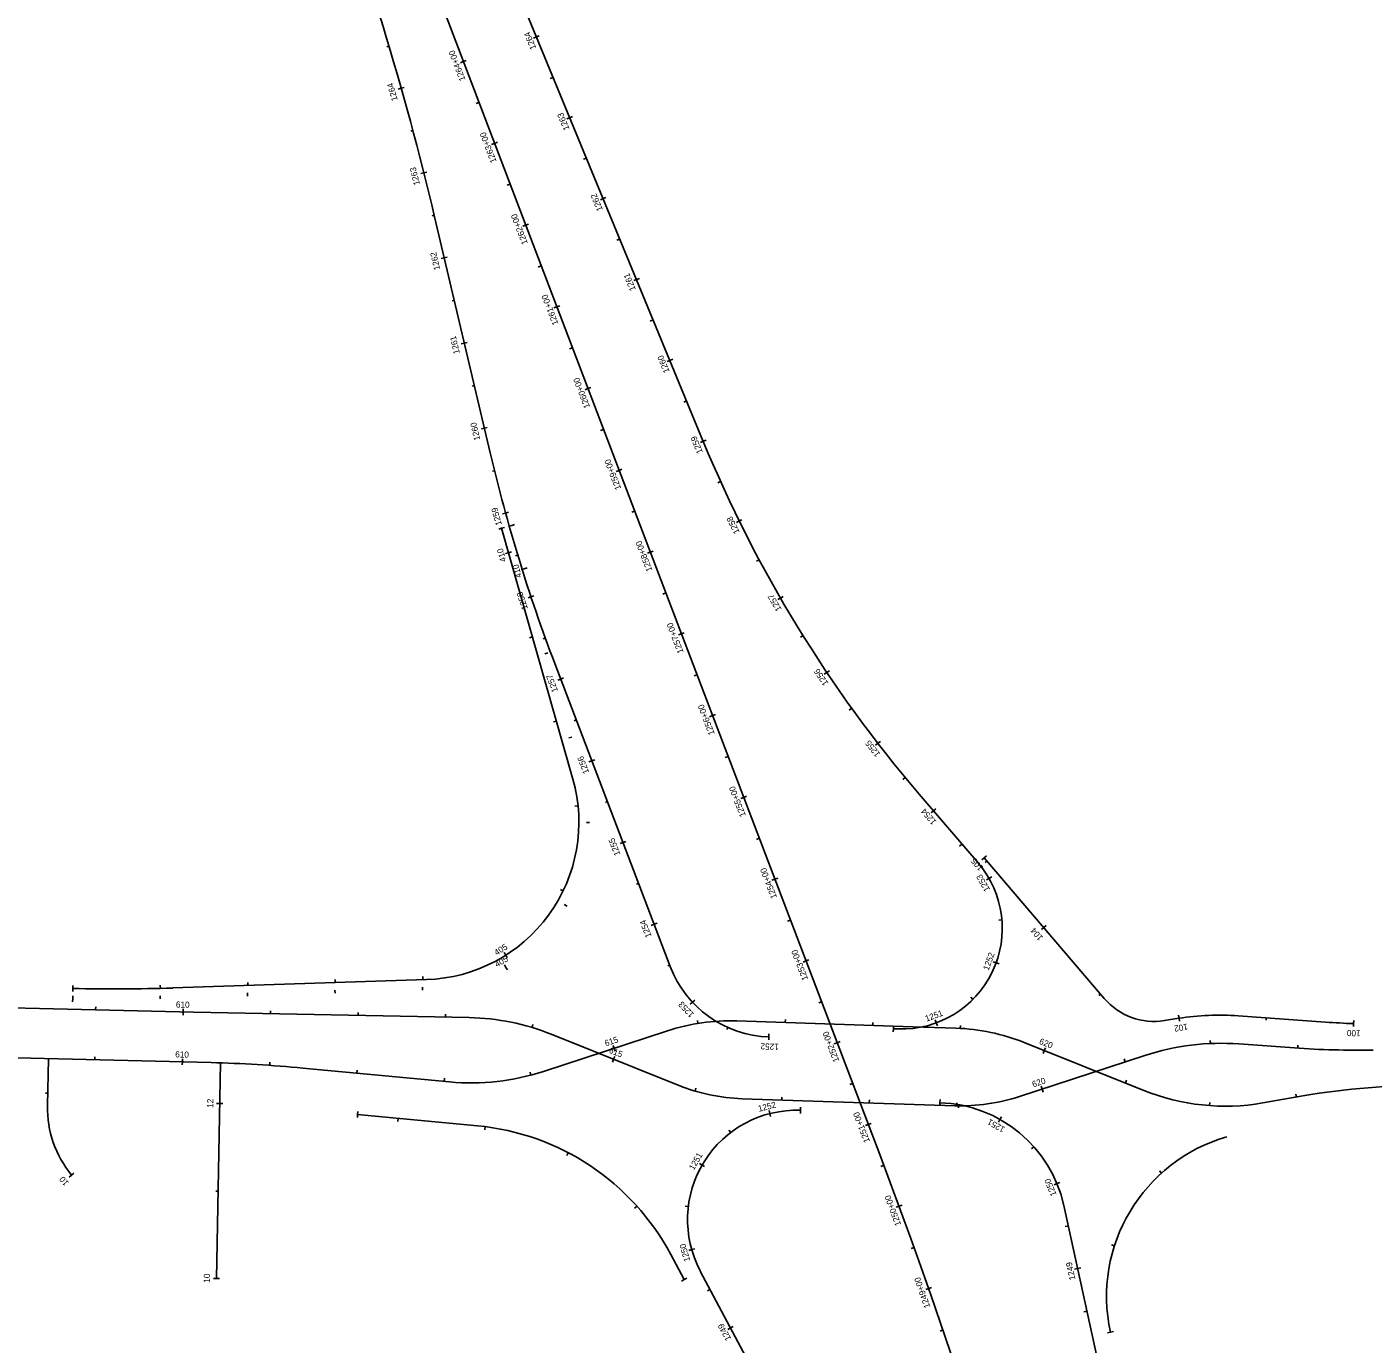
# Model space of a CAD drawing. Extents: x 596008 to 607538, y 326212 to 405053.
# Drawn here: x 602999 to 604538, y 349610 to 351115 of the extents above; entities that cross this region are included whole.
import ezdxf

# ---------------------------------------------------------------- set-up
doc = ezdxf.new("R2010")
doc.units = 0
for name, color, linetype in [('P_ALI', 7, 'Continuous'), ('P_ALI_200', 7, 'Continuous'), ('P_ALI_200_Sta', 7, 'Continuous'), ('P_ALI_200_Tic', 7, 'Continuous')]:
    doc.layers.add(name, color=color, linetype=linetype)

msp = doc.modelspace()

# ---------------------------------------------------------------- linework, layer by layer
at = {"layer": 'P_ALI'}
for points in [[(603772.4, 350641.6), (603324.3, 351728.4)], [(603528.9, 350628.5), (603465.4, 350898.3)], [(603623.4, 350255.6), (603541.9, 350542.5)], [(603734.7, 350041.4), (603602.8, 350387.7)], [(604086.5, 350159.8), (604019.2, 350238.5)], [(604230.7, 350005), (604093.3, 350165.6)], [(603166.2, 350016.9), (603456.2, 350026.5)], [(602805.1, 349998.4), (603189.8, 349989.1)], [(603189.8, 349989.1), (603504.9, 349983.1)], [(604315.9, 349982.3), (604299.5, 349979.6)], [(604483.5, 349978), (604383.8, 349985.1)], [(603589.8, 349921.5), (603731.6, 349967.9)], [(603810.6, 349979.2), (604011.8, 349972.6)], [(603989.7, 349970.3), (603995.3, 349970.1)], [(604011.8, 349972.6), (604061.2, 349970.9)], [(603598.7, 349964), (603743.9, 349905.7)], [(604139.2, 349954.5), (604275.8, 349899.7)], [(604384.5, 349953), (604447.9, 349948.4)], [(602670.3, 349944.6), (603210.1, 349931.6)], [(603023, 349882.4), (603024.3, 349936.1)], [(604133.8, 349892.9), (604277.1, 349939.8)], [(603216.1, 349684.8), (603220.7, 349931.3)], [(603314.9, 349925.4), (603482.5, 349909.6)], [(603817, 349890.3), (604059.8, 349882.3)], [(604411.8, 349885.5), (604457.5, 349893.5)], [(603514.4, 349859.4), (603377.4, 349872.3)], [(604246.7, 349484.4), (604184.5, 349768.1)], [(603750.5, 349683.6), (603735.3, 349712.1)], [(603879.4, 349486), (603769, 349693.4)]]:
    msp.add_lwpolyline(points, dxfattribs=at)
for centre, radius, start, end in [((600155.9, 350118.9), 3400, 13.2512, 20.8548), ((605378.3, 351064.1), 1900, 193.2512, 200.8548), ((605159.2, 351213.4), 1500, 202.4065, 220.5362), ((603450.3, 350206.4), 180, 271.8911, 15.857), ((603999.1, 350085), 115, 268.1133, 40.5362), ((603851.5, 350085.9), 125, 200.8548, 268.1133), ((603100.2, 352015.8), 2000, 268.6212, 271.8911), ((604287.7, 350053.7), 75, 220.5362, 279.0172), ((603499.9, 349718.1), 265, 68.1133, 88.9058), ((604362.4, 349688.9), 297, 85.8706, 99.0172), ((603803.1, 349749.3), 230, 88.1133, 108.1133), ((604053.6, 349741.1), 230, 68.1473, 88.1133), ((604553.2, 350943.4), 968, 265.8706, 267.7776), ((604364.3, 349673.7), 280, 85.8706, 108.1473), ((604519.9, 350945.8), 1000, 265.8706, 271.0298), ((603174, 348432), 1500, 84.6117, 88.6212), ((603507.4, 350173.4), 265, 264.6117, 288.1133), ((603824.1, 350105.2), 215, 248.1133, 268.1133), ((604595, 349105.4), 800, 89.1186, 99.8942), ((604066.9, 350097.2), 215, 268.1133, 288.1473), ((604368.9, 350131.8), 250, 248.1473, 279.8942), ((603143, 349879.5), 120, 178.6212, 219.6028), ((603879.4, 349752.2), 125, 88.1133, 208.0179), ((604038, 349735.9), 150, 12.3818, 88.1133), ((603488.1, 349580.6), 280, 28.0179, 84.6117), ((604423.3, 349664.2), 190, 106.0325, 192.3818)]:
    msp.add_arc(centre, radius, start, end, dxfattribs=at)
at = {"layer": 'P_ALI_200'}
msp.add_lwpolyline([(603974.1, 349826.7), (602314.7, 354182.5)], dxfattribs=at)
msp.add_arc((598624.1, 347788.6), 5725, 359.0183, 20.8548, dxfattribs=at)
at = {"layer": 'P_ALI_200_Sta'}
for points in [[(603581.8, 351104.1), (603578.5, 351102.7)], [(603585, 351105.4), (603581.8, 351104.1)], [(603581.8, 351104.1), (603581.8, 351104.1)], [(603498.2, 351075.8), (603494.9, 351074.5)], [(603501.5, 351077), (603498.2, 351075.8)], [(603498.2, 351075.8), (603498.2, 351075.8)], [(603600.8, 351057.8), (603597.6, 351056.5)], [(603427.3, 351045.3), (603423.9, 351044.3)], [(603430.6, 351046.2), (603427.3, 351045.3)], [(603427.3, 351045.3), (603427.3, 351045.3)], [(603516, 351029.1), (603512.7, 351027.8)], [(603619.9, 351011.6), (603616.6, 351010.3)], [(603623.1, 351012.9), (603619.9, 351011.6)], [(603619.9, 351011.6), (603619.9, 351011.6)], [(603533.8, 350982.3), (603530.5, 350981.1)], [(603537.1, 350983.6), (603533.8, 350982.3)], [(603533.8, 350982.3), (603533.8, 350982.3)], [(603638.9, 350965.4), (603635.7, 350964.1)], [(603456.5, 350949.5), (603453.1, 350948.7)], [(603453.1, 350948.7), (603449.7, 350947.8)], [(603453.1, 350948.7), (603453.1, 350948.7)], [(603551.6, 350935.6), (603548.3, 350934.4)], [(603658, 350919.2), (603654.8, 350917.8)], [(603661.2, 350920.5), (603658, 350919.2)], [(603658, 350919.2), (603658, 350919.2)], [(603569.4, 350888.9), (603566.1, 350887.6)], [(603572.7, 350890.1), (603569.4, 350888.9)], [(603569.4, 350888.9), (603569.4, 350888.9)], [(603677.1, 350872.9), (603673.8, 350871.6)], [(603476.4, 350851.4), (603473, 350850.6)], [(603479.8, 350852.2), (603476.4, 350851.4)], [(603476.4, 350851.4), (603476.4, 350851.4)], [(603587.2, 350842.2), (603583.9, 350840.9)], [(603696.1, 350826.7), (603692.9, 350825.4)], [(603699.4, 350828), (603696.1, 350826.7)], [(603696.1, 350826.7), (603696.1, 350826.7)], [(603608.3, 350796.7), (603605, 350795.4)], [(603605, 350795.4), (603601.7, 350794.2)], [(603605, 350795.4), (603605, 350795.4)], [(603715.2, 350780.5), (603711.9, 350779.2)], [(603499.3, 350754.1), (603495.9, 350753.3)], [(603502.7, 350754.9), (603499.3, 350754.1)], [(603499.3, 350754.1), (603499.3, 350754.1)], [(603622.8, 350748.7), (603619.5, 350747.5)], [(603734.2, 350734.3), (603731, 350732.9)], [(603737.5, 350735.6), (603734.2, 350734.3)], [(603734.2, 350734.3), (603734.2, 350734.3)], [(603640.6, 350702), (603637.3, 350700.8)], [(603643.9, 350703.2), (603640.6, 350702)], [(603640.6, 350702), (603640.6, 350702)], [(603753.3, 350688), (603750.1, 350686.7)], [(603525.6, 350657.6), (603522.2, 350656.8)], [(603522.2, 350656.8), (603518.8, 350656)], [(603522.2, 350656.8), (603522.2, 350656.8)], [(603658.4, 350655.3), (603655.1, 350654)], [(603772.4, 350641.8), (603769.1, 350640.5)], [(603775.6, 350643.1), (603772.4, 350641.8)], [(603772.4, 350641.8), (603772.4, 350641.8)], [(603676.2, 350608.5), (603672.9, 350607.3)], [(603679.5, 350609.8), (603676.2, 350608.5)], [(603676.2, 350608.5), (603676.2, 350608.5)], [(603792.2, 350595.9), (603789, 350594.5)], [(603546.4, 350559.7), (603543.1, 350558.8)], [(603549.8, 350560.7), (603546.4, 350559.7)], [(603546.4, 350559.7), (603546.4, 350559.7)], [(603694, 350561.8), (603690.7, 350560.6)], [(603813.5, 350550.7), (603810.4, 350549.1)], [(603816.6, 350552.2), (603813.5, 350550.7)], [(603813.5, 350550.7), (603813.5, 350550.7)], [(603541.9, 350542.5), (603538.6, 350541.5)], [(603545.3, 350543.4), (603541.9, 350542.5)], [(603541.9, 350542.5), (603541.9, 350542.5)], [(603553.5, 350545.7), (603550.1, 350544.8)], [(603556.8, 350546.7), (603553.5, 350545.7)], [(603553.5, 350545.7), (603553.5, 350545.7)], [(603549.9, 350514.4), (603546.5, 350513.4)], [(603553.3, 350515.3), (603549.9, 350514.4)], [(603549.9, 350514.4), (603549.9, 350514.4)], [(603711.8, 350515.1), (603708.5, 350513.9)], [(603715.1, 350516.3), (603711.8, 350515.1)], [(603711.8, 350515.1), (603711.8, 350515.1)], [(603836.3, 350506.2), (603833.3, 350504.6)], [(603567.6, 350496.1), (603564.2, 350495.1)], [(603571, 350497), (603567.6, 350496.1)], [(603567.6, 350496.1), (603567.6, 350496.1)], [(603575.5, 350464.1), (603572.2, 350463)], [(603578.8, 350465.2), (603575.5, 350464.1)], [(603575.5, 350464.1), (603575.5, 350464.1)], [(603729.6, 350468.4), (603726.3, 350467.1)], [(603860.6, 350462.5), (603857.6, 350460.8)], [(603863.7, 350464.3), (603860.6, 350462.5)], [(603860.6, 350462.5), (603860.6, 350462.5)], [(603577.2, 350418.2), (603573.9, 350417.2)], [(603747.4, 350421.7), (603744.1, 350420.4)], [(603750.7, 350422.9), (603747.4, 350421.7)], [(603747.4, 350421.7), (603747.4, 350421.7)], [(603886.4, 350419.7), (603883.4, 350417.8)], [(603594.9, 350399.9), (603591.5, 350398.9)], [(603609.5, 350370), (603606.2, 350368.8)], [(603612.8, 350371.3), (603609.5, 350370)], [(603609.5, 350370), (603609.5, 350370)], [(603765.2, 350374.9), (603761.9, 350373.7)], [(603913.5, 350377.7), (603910.6, 350375.7)], [(603916.5, 350379.6), (603913.5, 350377.7)], [(603913.5, 350377.7), (603913.5, 350377.7)], [(603942.1, 350336.6), (603939.3, 350334.6)], [(603604.6, 350322), (603601.2, 350321)], [(603783, 350328.2), (603779.7, 350327)], [(603786.3, 350329.4), (603783, 350328.2)], [(603783, 350328.2), (603783, 350328.2)], [(603622.2, 350303.7), (603618.9, 350302.7)], [(603972, 350296.6), (603969.2, 350294.4)], [(603974.8, 350298.7), (603972, 350296.6)], [(603972, 350296.6), (603972, 350296.6)], [(603645.1, 350276.6), (603641.8, 350275.3)], [(603648.4, 350277.8), (603645.1, 350276.6)], [(603645.1, 350276.6), (603645.1, 350276.6)], [(603800.8, 350281.5), (603797.5, 350280.2)], [(604003.2, 350257.5), (604000.5, 350255.3)], [(603818.6, 350234.8), (603815.3, 350233.5)], [(603821.9, 350236), (603818.6, 350234.8)], [(603818.6, 350234.8), (603818.6, 350234.8)], [(603629.3, 350225.2), (603625.8, 350224.9)], [(604035.5, 350219.4), (604032.9, 350217.1)], [(604038.2, 350221.6), (604035.5, 350219.4)], [(604035.5, 350219.4), (604035.5, 350219.4)], [(603642.3, 350206.1), (603638.8, 350206.1)], [(603680.7, 350183.1), (603677.4, 350181.9)], [(603684, 350184.4), (603680.7, 350183.1)], [(603680.7, 350183.1), (603680.7, 350183.1)], [(603836.4, 350188), (603833.1, 350186.8)], [(604068, 350181.4), (604065.4, 350179.1)], [(604093.3, 350165.6), (604090.7, 350163.4)], [(604096, 350167.9), (604093.3, 350165.6)], [(604093.3, 350165.6), (604093.3, 350165.6)], [(603854.2, 350141.3), (603850.9, 350140.1)], [(603857.5, 350142.6), (603854.2, 350141.3)], [(603854.2, 350141.3), (603854.2, 350141.3)], [(604098.9, 350142.2), (604095.9, 350140.4)], [(604102, 350143.9), (604098.9, 350142.2)], [(604098.9, 350142.2), (604098.9, 350142.2)], [(603612.3, 350128), (603609.1, 350129.5)], [(603616.7, 350110.6), (603613.6, 350112.4)], [(603716.3, 350089.7), (603713, 350088.4)], [(603719.6, 350090.9), (603716.3, 350089.7)], [(603716.3, 350089.7), (603716.3, 350089.7)], [(603872, 350094.6), (603868.7, 350093.3)], [(604113.7, 350094.8), (604110.2, 350094.5)], [(604164.1, 350088.3), (604161.5, 350086)], [(604161.5, 350086), (604158.8, 350083.7)], [(604161.5, 350086), (604161.5, 350086)], [(603546.6, 350054.3), (603544.7, 350057.3)], [(603546.9, 350040.5), (603545.2, 350043.5)], [(603546.6, 350054.3), (603546.6, 350054.3)], [(603548.4, 350051.4), (603546.6, 350054.3)], [(603889.8, 350047.9), (603886.5, 350046.6)], [(603893.1, 350049.1), (603889.8, 350047.9)], [(603889.8, 350047.9), (603889.8, 350047.9)], [(604107.1, 350045.6), (604103.8, 350046.8)], [(604107.1, 350045.6), (604107.1, 350045.6)], [(604110.4, 350044.4), (604107.1, 350045.6)], [(603351.9, 350023.1), (603351.8, 350026.6)], [(603451.9, 350026.4), (603451.8, 350029.9)], [(603546.9, 350040.5), (603546.9, 350040.5)], [(603548.7, 350037.5), (603546.9, 350040.5)], [(603052, 350016.4), (603052.1, 350019.9)], [(603052, 350016.4), (603052, 350016.4)], [(603052, 350012.9), (603052, 350016.4)], [(603152, 350016.5), (603151.9, 350020)], [(603251.7, 350007.7), (603251.6, 350011.2)], [(603252, 350019.8), (603251.9, 350023.3)], [(603351.6, 350011), (603351.5, 350014.5)], [(603451.6, 350014.3), (603451.5, 350017.8)], [(603051.7, 350000.9), (603051.8, 350004.4)], [(603051.8, 350004.4), (603051.8, 350007.9)], [(603051.8, 350004.4), (603051.8, 350004.4)], [(603151.7, 350004.5), (603151.7, 350008)], [(603760.1, 350000.6), (603757.5, 349998.3)], [(603762.6, 350003), (603760.1, 350000.6)], [(603760.1, 350000.6), (603760.1, 350000.6)], [(603907.6, 350001.1), (603904.3, 349999.9)], [(604080.5, 350003.8), (604078, 350006.3)], [(603078, 349991.8), (603078.1, 349995.3)], [(603177.9, 349985.9), (603178, 349989.4)], [(603178, 349989.4), (603178, 349992.9)], [(603178, 349989.4), (603178, 349989.4)], [(603277.9, 349987.4), (603278, 349990.9)], [(603377.9, 349985.5), (603378, 349989)], [(603477.9, 349983.6), (603478, 349987.1)], [(603866.1, 349977.4), (603866.2, 349980.9)], [(604038.7, 349977.1), (604037.5, 349980.4)], [(604315.6, 349985.7), (604316.1, 349982.3)], [(604316.1, 349982.3), (604316.7, 349978.8)], [(604316.1, 349982.3), (604316.1, 349982.3)], [(603576.8, 349971.7), (603577.8, 349975.1)], [(603766.3, 349976.4), (603765.7, 349979.8)], [(603966, 349974.1), (603966.1, 349977.6)], [(603989.5, 349966.8), (603989.7, 349970.3)], [(603989.7, 349970.3), (603989.8, 349973.8)], [(603989.7, 349970.3), (603989.7, 349970.3)], [(604038.7, 349977.1), (604038.7, 349977.1)], [(604039.9, 349973.8), (604038.7, 349977.1)], [(604066, 349970.7), (604066.2, 349974.2)], [(604515.6, 349976.2), (604515.5, 349972.7)], [(604515.8, 349979.7), (604515.6, 349976.2)], [(604515.6, 349976.2), (604515.6, 349976.2)], [(603670.5, 349947.9), (603669.4, 349951.3)], [(603847.4, 349961), (603847.3, 349957.5)], [(603847.5, 349964.5), (603847.4, 349961)], [(603847.4, 349961), (603847.4, 349961)], [(603925.4, 349954.4), (603922.1, 349953.2)], [(603928.7, 349955.7), (603925.4, 349954.4)], [(603925.4, 349954.4), (603925.4, 349954.4)], [(604352, 349953.5), (604351.8, 349957)], [(604451.8, 349948.2), (604452, 349951.7)], [(603077.1, 349934.8), (603077.2, 349938.3)], [(603177.1, 349932.4), (603177.2, 349935.9)], [(603668.6, 349932.1), (603669.9, 349935.4)], [(603669.9, 349935.4), (603671.2, 349938.6)], [(603669.9, 349935.4), (603669.9, 349935.4)], [(603670.5, 349947.9), (603670.5, 349947.9)], [(603671.6, 349944.6), (603670.5, 349947.9)], [(604160.8, 349942.1), (604162.1, 349945.4)], [(604162.1, 349945.4), (604163.4, 349948.6)], [(604162.1, 349945.4), (604162.1, 349945.4)], [(604254.6, 349932.4), (604253.5, 349935.8)], [(603177, 349928.9), (603177.1, 349932.4)], [(603177.1, 349932.4), (603177.1, 349932.4)], [(603277, 349928.5), (603277.2, 349932)], [(603376.6, 349919.6), (603376.9, 349923.1)], [(603575.3, 349917.3), (603574.4, 349920.6)], [(603476.2, 349910.2), (603476.5, 349913.7)], [(603943.2, 349907.7), (603939.9, 349906.4)], [(604159.6, 349901.3), (604158.5, 349904.6)], [(604254.9, 349908.1), (604256.2, 349911.4)], [(603763, 349899), (603764, 349902.4)], [(603862.2, 349888.8), (603862.3, 349892.3)], [(603962.1, 349885.5), (603962.2, 349889)], [(604043, 349889.3), (604042.9, 349885.8)], [(604159.6, 349901.3), (604159.6, 349901.3)], [(604160.7, 349898), (604159.6, 349901.3)], [(604450.2, 349892.2), (604449.6, 349895.6)], [(603219.8, 349884.7), (603216.3, 349884.8)], [(603219.8, 349884.7), (603219.8, 349884.7)], [(603223.3, 349884.7), (603219.8, 349884.7)], [(603377.8, 349875.8), (603377.4, 349872.3)], [(603848.6, 349873.3), (603847.7, 349876.7)], [(603848.6, 349873.3), (603848.6, 349873.3)], [(603849.4, 349869.9), (603848.6, 349873.3)], [(603883.4, 349873.6), (603883.5, 349877.1)], [(603883.5, 349877.1), (603883.6, 349880.6)], [(603883.5, 349877.1), (603883.5, 349877.1)], [(604042.9, 349885.8), (604042.8, 349882.3)], [(604042.9, 349885.8), (604042.9, 349885.8)], [(604062.1, 349882.2), (604062.1, 349885.7)], [(604064.6, 349883.5), (604064, 349880.1)], [(604351, 349882.4), (604351.3, 349885.9)], [(603377.4, 349872.3), (603377.1, 349868.8)], [(603377.4, 349872.3), (603377.4, 349872.3)], [(603423.7, 349867.9), (603423.4, 349864.4)], [(603523.3, 349858.4), (603522.8, 349854.9)], [(603961, 349861), (603957.7, 349859.7)], [(603964.3, 349862.2), (603961, 349861)], [(603961, 349861), (603961, 349861)], [(604111.4, 349866.7), (604109.7, 349863.7)], [(604113.1, 349869.8), (604111.4, 349866.7)], [(604111.4, 349866.7), (604111.4, 349866.7)], [(603803.8, 349851.7), (603801.7, 349854.5)], [(603618.2, 349828.6), (603616.5, 349825.5)], [(604150.2, 349835.5), (604147.5, 349833.1)], [(603771, 349814.4), (603768, 349816.2)], [(603771, 349814.4), (603771, 349814.4)], [(603774, 349812.7), (603771, 349814.4)], [(603978.8, 349814.2), (603975.5, 349813)], [(603050.5, 349803), (603047.8, 349800.7)], [(603053.2, 349805.2), (603050.5, 349803)], [(603050.5, 349803), (603050.5, 349803)], [(604296, 349805.2), (604293.6, 349807.8)], [(604176.6, 349793.3), (604173.3, 349791.9)], [(604179.8, 349794.6), (604176.6, 349793.3)], [(604176.6, 349793.3), (604176.6, 349793.3)], [(603696.7, 349767.5), (603694, 349765.1)], [(603755.3, 349767.3), (603751.8, 349767.7)], [(603996.3, 349767.4), (603993, 349766.2)], [(603999.6, 349768.6), (603996.3, 349767.4)], [(603996.3, 349767.4), (603996.3, 349767.4)], [(604189.5, 349745.1), (604186.1, 349744.3)], [(603762.6, 349718.8), (603759.2, 349717.8)], [(604013.4, 349720.4), (604010.1, 349719.2)], [(604242.4, 349722.2), (604239, 349723.2)], [(603759.2, 349717.8), (603755.8, 349716.8)], [(603759.2, 349717.8), (603759.2, 349717.8)], [(604200.2, 349696.2), (604196.8, 349695.5)], [(604203.7, 349697), (604200.2, 349696.2)], [(604200.2, 349696.2), (604200.2, 349696.2)], [(603216.1, 349684.8), (603212.6, 349684.8)], [(603216.1, 349684.8), (603216.1, 349684.8)], [(603219.6, 349684.7), (603216.1, 349684.8)], [(603750.5, 349683.6), (603747.4, 349681.9)], [(603753.6, 349685.2), (603750.5, 349683.6)], [(603750.5, 349683.6), (603750.5, 349683.6)], [(604030, 349673.3), (604026.7, 349672.1)], [(604033.3, 349674.4), (604030, 349673.3)], [(604030, 349673.3), (604030, 349673.3)], [(603780.2, 349672.5), (603777.1, 349670.9)], [(604211, 349647.4), (604207.5, 349646.6)], [(603803.7, 349628.4), (603800.6, 349626.7)], [(603806.7, 349630), (603803.7, 349628.4)], [(603803.7, 349628.4), (603803.7, 349628.4)], [(604046.3, 349626), (604043, 349624.8)], [(604237.7, 349623.4), (604234.3, 349622.7)], [(604241.1, 349624.2), (604237.7, 349623.4)], [(604237.7, 349623.4), (604237.7, 349623.4)]]:
    msp.add_lwpolyline(points, dxfattribs=at)
at = {"layer": 'P_ALI_200_Tic'}
for points in [[(603413.3, 351093.3), (603410.9, 351092.6)], [(603440.5, 350997.1), (603438.1, 350996.4)], [(603464.9, 350900.1), (603462.5, 350899.5)], [(603487.9, 350802.8), (603485.4, 350802.2)], [(603510.8, 350705.4), (603508.3, 350704.9)], [(603533.8, 350608.1), (603531.4, 350607.5)], [(603560.4, 350511.7), (603558, 350511)], [(603591.9, 350416.9), (603589.6, 350416)], [(603627.3, 350323.3), (603625, 350322.4)], [(603662.9, 350229.9), (603660.6, 350229)], [(604096.5, 350162), (604094.6, 350160.4)], [(603698.5, 350136.4), (603696.2, 350135.5)], [(603734.1, 350043), (603731.8, 350042.1)], [(604226.4, 350010), (604224.6, 350008.4)], [(604415.8, 349982.8), (604415.7, 349980.3)], [(603800.5, 349971.8), (603799.5, 349969.5)], [(603023.4, 349896.5), (603020.9, 349896.6)], [(603218, 349784.7), (603215.5, 349784.8)]]:
    msp.add_lwpolyline(points, dxfattribs=at)

# ---------------------------------------------------------------- texts
at = {"layer": 'P_ALI_200_Sta'}
for s, height, rotation, p in [('1264', 7, 112.4065, (603581.7, 351091.2)), ('1264+00', 7, 110.8548, (603500.8, 351055.1)), ('1264', 7, 105.8109, (603423.3, 351031.9)), ('1263', 7, 112.4065, (603619.7, 350998.9)), ('1263+00', 7, 110.8548, (603536.4, 350961.6)), ('1263', 7, 104.1257, (603448.7, 350935.5)), ('1262', 7, 112.4065, (603657.8, 350906.5)), ('1262+00', 7, 110.8548, (603572, 350868.2)), ('1262', 7, 103.2512, (603471.8, 350838.4)), ('1261', 7, 112.4065, (603695.4, 350815.4)), ('1261+00', 7, 110.8548, (603607, 350776.1)), ('1261', 7, 103.2512, (603494.3, 350742.5)), ('1260', 7, 112.4065, (603734.1, 350721.6)), ('1260+00', 7, 110.8548, (603643.2, 350681)), ('1260', 7, 103.2512, (603517.6, 350643.7)), ('1259', 7, 112.4065, (603772.1, 350629.3)), ('1259+00', 7, 110.8548, (603678.8, 350587.8)), ('1259', 7, 105.3925, (603542.3, 350546.7)), ('1258', 7, 116.2185, (603814.2, 350538)), ('410', 0.0000000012, 105.857, (603537.1, 350541.1)), ('410', 0.0000000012, 105.857, (603548.7, 350544.4)), ('410', 7, 105.857, (603547.4, 350505)), ('1258+00', 7, 110.8548, (603714.4, 350494.4)), ('410', 7, 105.857, (603565.1, 350486.7)), ('1258', 7, 108.408, (603572.1, 350450.6)), ('1257', 7, 120.0383, (603862.2, 350449.9)), ('1257+00', 7, 110.8548, (603750, 350400.9)), ('1256', 7, 123.858, (603915.8, 350365.3)), ('1257', 7, 110.8548, (603606.6, 350356.5)), ('1256+00', 7, 110.8548, (603785.6, 350307.5)), ('1255', 7, 127.6777, (603975.2, 350284.3)), ('1256', 7, 110.8548, (603642.2, 350263.2)), ('1255+00', 7, 110.8548, (603821.2, 350214)), ('1254', 7, 130.5362, (604039.4, 350207.1)), ('1255', 7, 110.8548, (603677.8, 350169.6)), ('105', 7, 130.5362, (604093.1, 350154.4)), ('1254+00', 7, 110.8548, (603856.8, 350120.6)), ('1253', 7, 119.7778, (604100.4, 350129.5)), ('1254', 7, 110.8548, (603713.5, 350076)), ('104', 7, 130.5362, (604161.3, 350074.6)), ('405', 7, 32.339, (603536.3, 350053.7)), ('1253+00', 7, 110.8548, (603892.4, 350027.1)), ('1252', 7, 69.9554, (604098.4, 350036.4)), ('405', 7, 30.2317, (603536.6, 350040.3)), ('400', 0.0000000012, 358.6212, (603052.2, 350021.4)), ('400', 0.0000000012, 358.6212, (603051.9, 350009.4)), ('610', 7, 358.6212, (603169.7, 349994.6)), ('1253', 7, 133.0052, (603762.6, 349987)), ('1251', 7, 20.133, (604027.4, 349978.3)), ('1252+00', 7, 110.8548, (603928, 349933.7)), ('1250', 0.0000000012, 358.1133, (603989.8, 349975.3)), ('102', 7, 188.9667, (604325.5, 349976.2)), ('100', 7, 177.7776, (604523.7, 349968.4)), ('615', 7, 18.1133, (603661, 349950.1)), ('1252', 7, 178.1133, (603858.8, 349953.1)), ('620', 7, 338.1473, (604155.6, 349953.3)), ('610', 7, 358.6212, (603168.9, 349937.6)), ('615', 7, 338.1133, (603664, 349943.1)), ('620', 7, 18.1473, (604149.5, 349903.3)), ('12', 7, 88.9261, (603212.3, 349879.9)), ('1252', 7, 14.2823, (603836, 349875.3)), ('1252', 0.0000000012, 358.1133, (603883.7, 349882.1)), ('1251+00', 7, 110.8548, (603963, 349841.6)), ('1251', 0.0000000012, 178.1133, (604042.7, 349880.8)), ('304', 0.0000000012, 174.6117, (603377, 349867.3)), ('1251', 7, 150.6763, (604117.8, 349857.4)), ('1251', 7, 60.1189, (603761.6, 349808.1)), ('10', 7, 129.6028, (603047.9, 349794.3)), ('1250', 7, 112.4791, (604176.4, 349780.6)), ('1250+00', 7, 110.2213, (603998.7, 349746.4)), ('1250', 7, 105.9555, (603757.6, 349705.2)), ('1249', 7, 102.3818, (604197.8, 349683.9)), ('10', 7, 88.9261, (603208.5, 349679.9)), ('300', 0.0000000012, 118.0179, (603746.1, 349681.2)), ('1249+00', 7, 109.2205, (604032, 349652.4)), ('1249', 7, 118.0179, (603804.6, 349615.9)), ('200', 0.0000000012, 102.3818, (604232.8, 349622.4))]:
    msp.add_text(s, height=height, rotation=rotation, dxfattribs=at).set_placement(p)

doc.saveas('drawing.dxf')
